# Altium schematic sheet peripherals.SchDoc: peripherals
size A3; DocumentNumber: MB1144; Revision: B-02; SheetNumber: 15; SheetTotal: 25; PageSetup: Record=PageOptions|CenterHorizontal=True|CenterVertical=True|PrintScale=1.39|XCorrection=1.00|YCorrection=1.00|PrintKind=1|BorderSize=5000000|LeftOffset=0|BottomOffset=0|Orientation=2|PaperLength=1000|PaperWidth=1000|Scale=100|PaperSource=264|PrintQuality=600|MediaType=1|DitherType=10|PaperKind=A3|PrintScaleMode=1; Project: STM32L476G-EVAL
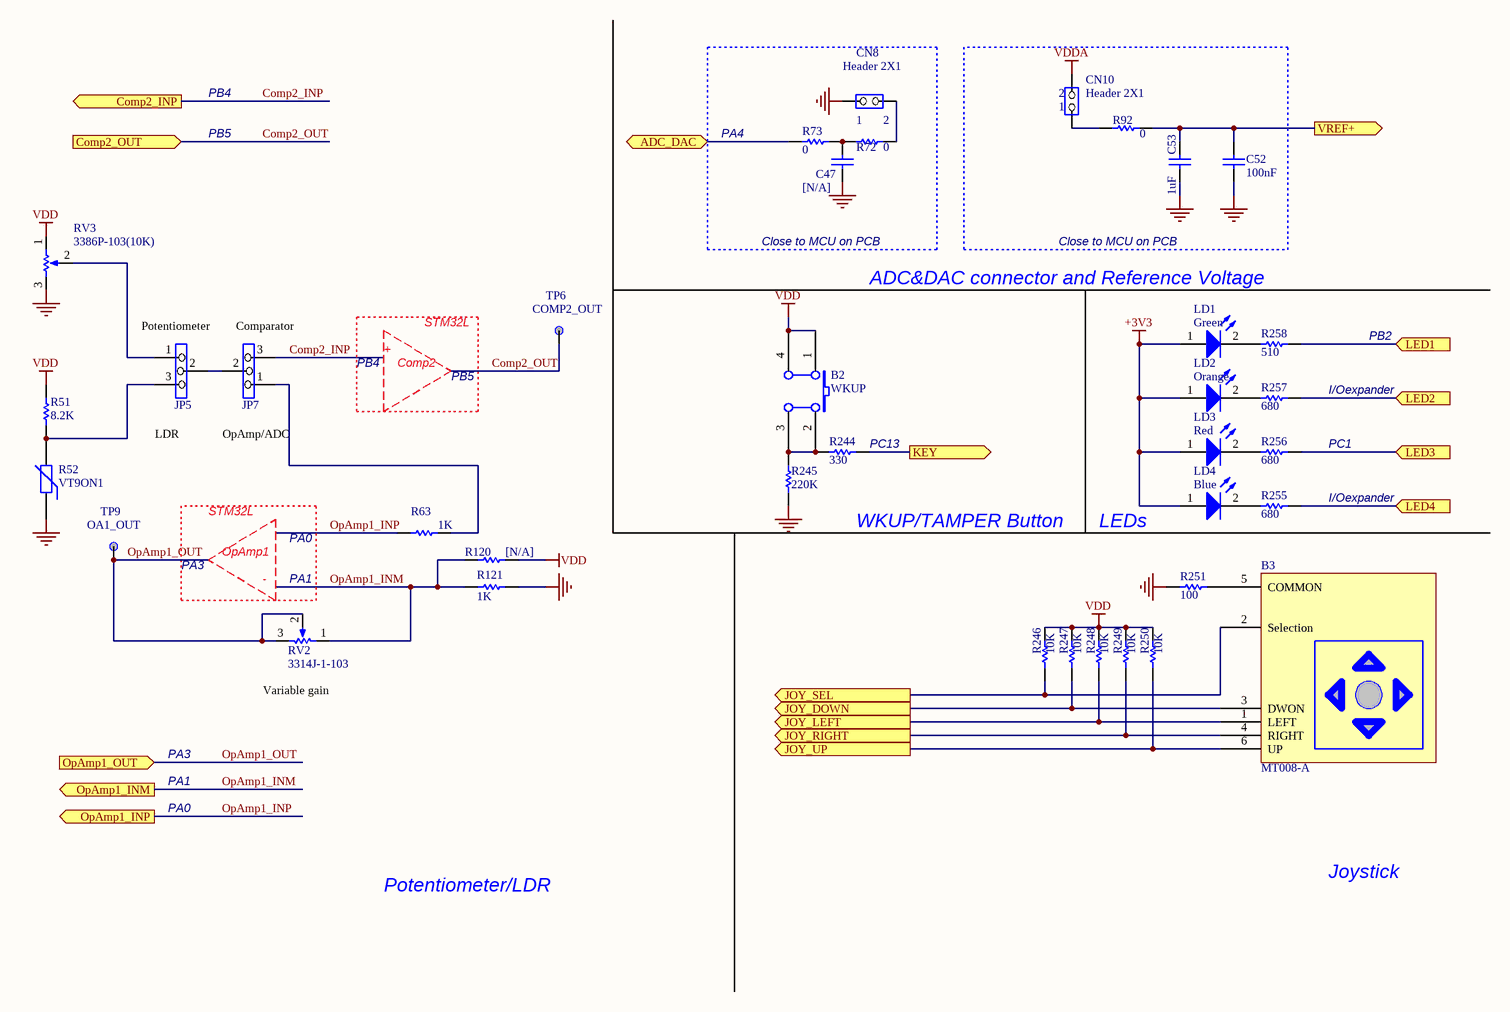
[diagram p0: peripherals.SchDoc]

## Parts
B2  WKUP  [PB10]
B3  MT008-A  [MT-008A]
C47  [N/A]  [0603C]
C52  100nF  [0402C]
C53  1uF  [0603C]
CN8  Header 2X1  [SIP2]
CN10  Header 2X1  [SIP2]
JP5  Header 3X1  [SIP3]  (value not drawn)
JP7  Header 3X1  [SIP3]  (value not drawn)
LD1  Green  [0603D]
LD2  Orange  [0603D]
LD3  Red  [0603D]
LD4  Blue  [0603D]
R51  8.2K  [0402R]
R52  VT9ON1  [PVT901]
R63  1K  [0402R]
R72  0  [0603R]
R73  0  [0603R]
R92  0  [0603R]
R120  [N/A]  [0603R]
R121  1K  [0402R]
R244  330  [0402R]
R245  220K  [0402R]
R246  10K  [0402R]
R247  10K  [0402R]
R248  10K  [0402R]
R249  10K  [0402R]
R250  10K  [0402R]
R251  100  [0402R]
R255  680  [0402R]
R256  680  [0402R]
R257  680  [0402R]
R258  510  [0402R]
RV2  3314J-1-103  [PTF_3314J]
RV3  3386P-103(10K)  [3386P]
TP6  TP Name: COMP2_OUT  [TP]  (hidden comment: [N/A])
TP9  TP Name: OA1_OUT  [TP]  (hidden comment: [N/A])

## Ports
ADC_DAC (bidir), Comp2_INP (out), Comp2_OUT (in), JOY_DOWN (out), JOY_LEFT (out), JOY_RIGHT (out), JOY_SEL (out), JOY_UP (out), KEY (out), LED1 (in), LED2 (in), LED3 (in), LED4 (in), OpAmp1_INM (out), OpAmp1_INP (out), OpAmp1_OUT (in), VREF+ (out)

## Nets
+3V3: LD1.1(A) LD2.1(A) LD3.1(A) LD4.1(A)
GND: C47.1 C52.1 C53.2 CN8.1(COMMON) R52.1 R121.1 R245.2 R251.1 RV3.3(TOP)
VDD: B2.1(A0) B2.4(A1) R51.2 R120.2 R246.1 R247.2 R248.2 R249.2 R250.2 RV3.1(BOT)
VDDA: CN10.2(NO)
ADC_DAC: R73.1 ; port ADC_DAC
Comp2_INP: JP7.3 ; port Comp2_INP
Comp2_OUT: TP6.1 ; port Comp2_OUT
JOY_DOWN: B3.3(DWON) R247.1 ; port JOY_DOWN
JOY_LEFT: B3.1(LEFT) R248.1 ; port JOY_LEFT
JOY_RIGHT: B3.4(RIGHT) R249.1 ; port JOY_RIGHT
JOY_SEL: B3.2(Selection) R246.2 ; port JOY_SEL
JOY_UP: B3.6(UP) R250.1 ; port JOY_UP
KEY: R244.2 ; port KEY
LED1: R258.1 ; port LED1
LED2: R257.1 ; port LED2
LED3: R256.1 ; port LED3
LED4: R255.1 ; port LED4
OpAmp1_INM: R120.1 R121.2 RV2.1(BOT) ; port OpAmp1_INM
OpAmp1_INP: R63.2 ; port OpAmp1_INP
OpAmp1_OUT: RV2.2(TAP) RV2.3(TOP) TP9.1 ; port OpAmp1_OUT
VREF+: C52.2 C53.1 R92.2 ; port VREF+
NetB2_2: B2.2(B0) B2.3(B1) R244.1 R245.1
NetB3_5: B3.5(COMMON) R251.2
NetC47_2: C47.2 R72.1 R73.2
NetCN8_2: CN8.2(NO) R72.2
NetCN10_1: CN10.1(COMMON) R92.1
NetJP5_1: JP5.1 RV3.2(TAP)
NetJP5_2: JP5.2 JP7.2
NetJP5_3: JP5.3 R51.1 R52.2
NetJP7_1: JP7.1 R63.1
NetLD1_2: LD1.2(K) R258.2
NetLD2_2: LD2.2(K) R257.2
NetLD3_2: LD3.2(K) R256.2
NetLD4_2: LD4.2(K) R255.2

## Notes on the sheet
- PB4
- (near CN10) 2
- PB5
- PA4
- 1
- 2
- (near CN10) 1
- Close to MCU on PCB
- ADC&DAC connector and Reference Voltage
- Potentiometer
- (near JP7) Comparator
- +
- Comp2
- STM32L
- PB2
- LDR
- OpAmp/ADC
- I/Oexpander
- (near R244) PC13
- PC1
- PA3
- OpAmp1
- PA0
- WKUP/TAMPER Button
- LEDs
- (near RV2) -
- (near RV2) PA1
- (near RV2) Variable gain
- PA1
- Potentiometer/LDR
- Joystick

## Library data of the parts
B2 = SW PUSHBUTTON: SE PUSHBUTTON; Ordered by: Subcon; Assembly: Blue; ECCN_US/EU: NA
B3 = MT-008A: Ordered by: Subcon; Assembly: with button; ECCN_US/EU: NA
C47 = cap: Capacitor; Value: 100pF; Ordered by: Subcon; ECCN_US/EU: NA; Fitted: NO
C52 = Cap: Capacitor; Value: 10nF; Ordered by: Subcon; ECCN_US/EU: NA
C53 = CAP: Capacitor; Value: 100nF; Ordered by: Subcon; ECCN_US/EU: NA
CN8 CN10 = JP2: Ordered by: Subcon; ECCN_US/EU: NA
JP5 JP7 = Jumper3: Ordered by: Subcon; ECCN_US/EU: NA
LD1-LD4 = LED2: Typical RED, GREEN, YELLOW, AMBER GaAs LED; Ordered by: Subcon; ECCN_US/EU: NA
R51 R72 R73 R92 R244 R246-R251 R255-R258 = Res1: Resistor; Value: 1K; Ordered by: Subcon; ECCN_US/EU: NA
R52 = Res Varistor: Varistor (Voltage-Sensitive Resistor); ECCN_US/EU: NA; Ordered by: Subcon
R63 R121 = Res1: Resistor; Ordered by: Subcon; ECCN_US/EU: NA
R120 = Res1: Resistor; Value: 1K; Ordered by: Subcon; ECCN_US/EU: NA; Fitted: NO
R245 = res1: Resistor; Value: 1K; Ordered by: Subcon; ECCN_US/EU: NA
RV2 = RV: Potentiometer 10K; Ordered by: Subcon; Comments: adjustable 10K potentiometer; ECCN_US/EU: NA
RV3 = RV: Potentiometer 10K; Ordered by: Subcon; Comments: 10K potentiometer; ECCN_US/EU: NA
TP6 TP9 = TP: Ordered by: Subcon; Fitted or not fitted: NO; ECCN_US/EU: NA; Fitted: NO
